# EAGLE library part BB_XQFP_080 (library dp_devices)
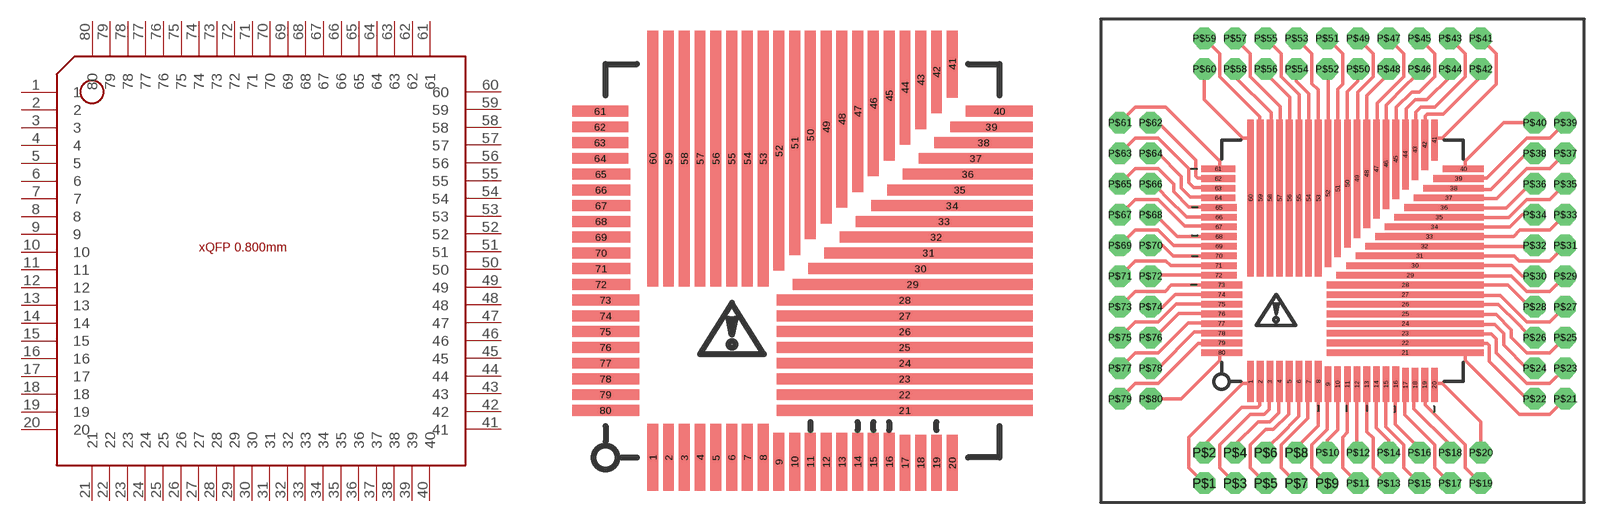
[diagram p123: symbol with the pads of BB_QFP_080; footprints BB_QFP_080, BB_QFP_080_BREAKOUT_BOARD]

Designator prefix -

## BB_XQFP_080  [BB_QFP_080]
1  1
2  2
3  3
4  4
5  5
6  6
7  7
8  8
9  9
10  10
11  11
12  12
13  13
14  14
15  15
16  16
17  17
18  18
19  19
20  20
21  21
22  22
23  23
24  24
25  25
26  26
27  27
28  28
29  29
30  30
31  31
32  32
33  33
34  34
35  35
36  36
37  37
38  38
39  39
40  40
41  41
42  42
43  43
44  44
45  45
46  46
47  47
48  48
49  49
50  50
51  51
52  52
53  53
54  54
55  55
56  56
57  57
58  58
59  59
60  60
61  61
62  62
63  63
64  64
65  65
66  66
67  67
68  68
69  69
70  70
71  71
72  72
73  73
74  74
75  75
76  76
77  77
78  78
79  79
80  80

## BB_XQFP_080BB  [BB_QFP_080_BREAKOUT_BOARD]
P$1  1
P$2  2
P$3  3
P$4  4
P$5  5
P$6  6
P$7  7
P$8  8
P$9  9
P$10  10
P$11  11
P$12  12
P$13  13
P$14  14
P$15  15
P$16  16
P$17  17
P$18  18
P$19  19
P$20  20
P$21  21
P$22  22
P$23  23
P$24  24
P$25  25
P$26  26
P$27  27
P$28  28
P$29  29
P$30  30
P$31  31
P$32  32
P$33  33
P$34  34
P$35  35
P$36  36
P$37  37
P$38  38
P$39  39
P$40  40
P$41  41
P$42  42
P$43  43
P$44  44
P$45  45
P$46  46
P$47  47
P$48  48
P$49  49
P$50  50
P$51  51
P$52  52
P$53  53
P$54  54
P$55  55
P$56  56
P$57  57
P$58  58
P$59  59
P$60  60
P$61  61
P$62  62
P$63  63
P$64  64
P$65  65
P$66  66
P$67  67
P$68  68
P$69  69
P$70  70
P$71  71
P$72  72
P$73  73
P$74  74
P$75  75
P$76  76
P$77  77
P$78  78
P$79  79
P$80  80

## Footprint BB_QFP_080 (pad centres in mm)
QFP 0.8 mm pitch 32p (7mm sq) 44p (10mm sq) 64p (14mm sq) 80p (16.5mm sq) CC-BY-SA
smd 0.55 x 3.405: 1 -7.6,-9.998; 2 -6.8,-9.998; 3 -6,-9.998; 4 -5.2,-9.998; 5 -4.4,-9.998; 6 -3.6,-9.998; 7 -2.8,-9.998; 8 -2,-9.998; 41 7.6,9.997
smd 0.55 x 2.95: 9 -1.2,-10.225; 10 -0.4,-10.225; 11 0.4,-10.225; 12 1.2,-10.225; 13 2,-10.225; 14 2.8,-10.225; 15 3.6,-10.225; 16 4.4,-10.225
smd 0.55 x 2.85: 17 5.2,-10.275; 18 6,-10.275; 19 6.8,-10.275; 20 7.6,-10.275
smd 13.005 x 0.55: 21 5.197,-7.6; 22 5.197,-6.8; 23 5.197,-6; 24 5.197,-5.2; 25 5.197,-4.4; 26 5.197,-3.6; 27 5.197,-2.8; 28 5.197,-2
smd 12.205 x 0.55: 29 5.597,-1.2
smd 11.405 x 0.55: 30 5.997,-0.4
smd 10.605 x 0.55: 31 6.397,0.4
smd 9.805 x 0.55: 32 6.797,1.2
smd 9.005 x 0.55: 33 7.197,2
smd 8.205 x 0.55: 34 7.597,2.8
smd 7.405 x 0.55: 35 7.997,3.6
smd 6.605 x 0.55: 36 8.397,4.4
smd 5.805 x 0.55: 37 8.797,5.2
smd 5.005 x 0.55: 38 9.197,6
smd 4.205 x 0.55: 39 9.597,6.8
smd 3.405 x 0.55: 40 9.997,7.6; 73 -9.998,-2; 74 -9.998,-2.8; 75 -9.998,-3.6; 76 -9.998,-4.4; 77 -9.998,-5.2; 78 -9.998,-6; 79 -9.998,-6.8; 80 -9.998,-7.6
smd 0.55 x 4.205: 42 6.8,9.597
smd 0.55 x 5.005: 43 6,9.197
smd 0.55 x 5.805: 44 5.2,8.797
smd 0.55 x 6.605: 45 4.4,8.397
smd 0.55 x 7.405: 46 3.6,7.997
smd 0.55 x 8.205: 47 2.8,7.597
smd 0.55 x 9.005: 48 2,7.197
smd 0.55 x 9.805: 49 1.2,6.797
smd 0.55 x 10.605: 50 0.4,6.397
smd 0.55 x 11.405: 51 -0.4,5.997
smd 0.55 x 12.205: 52 -1.2,5.597
smd 0.55 x 13.005: 53 -2,5.198; 54 -2.8,5.198; 55 -3.6,5.198; 56 -4.4,5.198; 57 -5.2,5.198; 58 -6,5.198; 59 -6.8,5.198; 60 -7.6,5.198
smd 2.85 x 0.55: 61 -10.275,7.6; 62 -10.275,6.8; 63 -10.275,6; 64 -10.275,5.2
smd 2.95 x 0.55: 65 -10.225,4.4; 66 -10.225,3.6; 67 -10.225,2.8; 68 -10.225,2; 69 -10.225,1.2; 70 -10.225,0.4; 71 -10.225,-0.4; 72 -10.225,-1.2

## Footprint BB_QFP_080_BREAKOUT_BOARD (pad centres in mm)
QFP 0.8 mm pitch 32p (7mm sq) 44p (10mm sq) 64p (14mm sq) 80p (16.5mm sq) CC-BY-SA
smd 0.55 x 3.405: 1 -7.6,-9.998; 2 -6.8,-9.998; 3 -6,-9.998; 4 -5.2,-9.998; 5 -4.4,-9.998; 6 -3.6,-9.998; 7 -2.8,-9.998; 8 -2,-9.998; 41 7.6,9.997
smd 0.55 x 2.95: 9 -1.2,-10.225; 10 -0.4,-10.225; 11 0.4,-10.225; 12 1.2,-10.225; 13 2,-10.225; 14 2.8,-10.225; 15 3.6,-10.225; 16 4.4,-10.225
smd 0.55 x 2.85: 17 5.2,-10.275; 18 6,-10.275; 19 6.8,-10.275; 20 7.6,-10.275
smd 13.005 x 0.55: 21 5.197,-7.6; 22 5.197,-6.8; 23 5.197,-6; 24 5.197,-5.2; 25 5.197,-4.4; 26 5.197,-3.6; 27 5.197,-2.8; 28 5.197,-2
smd 12.205 x 0.55: 29 5.597,-1.2
smd 11.405 x 0.55: 30 5.997,-0.4
smd 10.605 x 0.55: 31 6.397,0.4
smd 9.805 x 0.55: 32 6.797,1.2
smd 9.005 x 0.55: 33 7.197,2
smd 8.205 x 0.55: 34 7.597,2.8
smd 7.405 x 0.55: 35 7.997,3.6
smd 6.605 x 0.55: 36 8.397,4.4
smd 5.805 x 0.55: 37 8.797,5.2
smd 5.005 x 0.55: 38 9.197,6
smd 4.205 x 0.55: 39 9.597,6.8
smd 3.405 x 0.55: 40 9.997,7.6; 73 -9.998,-2; 74 -9.998,-2.8; 75 -9.998,-3.6; 76 -9.998,-4.4; 77 -9.998,-5.2; 78 -9.998,-6; 79 -9.998,-6.8; 80 -9.998,-7.6
smd 0.55 x 4.205: 42 6.8,9.597
smd 0.55 x 5.005: 43 6,9.197
smd 0.55 x 5.805: 44 5.2,8.797
smd 0.55 x 6.605: 45 4.4,8.397
smd 0.55 x 7.405: 46 3.6,7.997
smd 0.55 x 8.205: 47 2.8,7.597
smd 0.55 x 9.005: 48 2,7.197
smd 0.55 x 9.805: 49 1.2,6.797
smd 0.55 x 10.605: 50 0.4,6.397
smd 0.55 x 11.405: 51 -0.4,5.997
smd 0.55 x 12.205: 52 -1.2,5.597
smd 0.55 x 13.005: 53 -2,5.198; 54 -2.8,5.198; 55 -3.6,5.198; 56 -4.4,5.198; 57 -5.2,5.198; 58 -6,5.198; 59 -6.8,5.198; 60 -7.6,5.198
smd 2.85 x 0.55: 61 -10.275,7.6; 62 -10.275,6.8; 63 -10.275,6; 64 -10.275,5.2
smd 2.95 x 0.55: 65 -10.225,4.4; 66 -10.225,3.6; 67 -10.225,2.8; 68 -10.225,2; 69 -10.225,1.2; 70 -10.225,0.4; 71 -10.225,-0.4; 72 -10.225,-1.2
drill 1.016 pad 1.778 octagon: P$1 -11.43,-18.415; P$2 -11.43,-15.875; P$3 -8.89,-18.415; P$4 -8.89,-15.875; P$5 -6.35,-18.415; P$6 -6.35,-15.875; P$7 -3.81,-18.415; P$8 -3.81,-15.875; P$9 -1.27,-18.415; P$10 -1.27,-15.875; P$11 1.27,-18.415; P$12 1.27,-15.875; P$13 3.81,-18.415; P$14 3.81,-15.875; P$15 6.35,-18.415; P$16 6.35,-15.875; P$17 8.89,-18.415; P$18 8.89,-15.875; P$19 11.43,-18.415; P$20 11.43,-15.875; P$21 18.415,-11.43; P$22 15.875,-11.43; P$23 18.415,-8.89; P$24 15.875,-8.89; P$25 18.415,-6.35; P$26 15.875,-6.35; P$27 18.415,-3.81; P$28 15.875,-3.81; P$29 18.415,-1.27; P$30 15.875,-1.27; P$31 18.415,1.27; P$32 15.875,1.27; P$33 18.415,3.81; P$34 15.875,3.81; P$35 18.415,6.35; P$36 15.875,6.35; P$37 18.415,8.89; P$38 15.875,8.89; P$39 18.415,11.43; P$40 15.875,11.43; P$41 11.43,18.415; P$42 11.43,15.875; P$43 8.89,18.415; P$44 8.89,15.875; P$45 6.35,18.415; P$46 6.35,15.875; P$47 3.81,18.415; P$48 3.81,15.875; P$49 1.27,18.415; P$50 1.27,15.875; P$51 -1.27,18.415; P$52 -1.27,15.875; P$53 -3.81,18.415; P$54 -3.81,15.875; P$55 -6.35,18.415; P$56 -6.35,15.875; P$57 -8.89,18.415; P$58 -8.89,15.875; P$59 -11.43,18.415; P$60 -11.43,15.875; P$61 -18.415,11.43; P$62 -15.875,11.43; P$63 -18.415,8.89; P$64 -15.875,8.89; P$65 -18.415,6.35; P$66 -15.875,6.35; P$67 -18.415,3.81; P$68 -15.875,3.81; P$69 -18.415,1.27; P$70 -15.875,1.27; P$71 -18.415,-1.27; P$72 -15.875,-1.27; P$73 -18.415,-3.81; P$74 -15.875,-3.81; P$75 -18.415,-6.35; P$76 -15.875,-6.35; P$77 -18.415,-8.89; P$78 -15.875,-8.89; P$79 -18.415,-11.43; P$80 -15.875,-11.43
